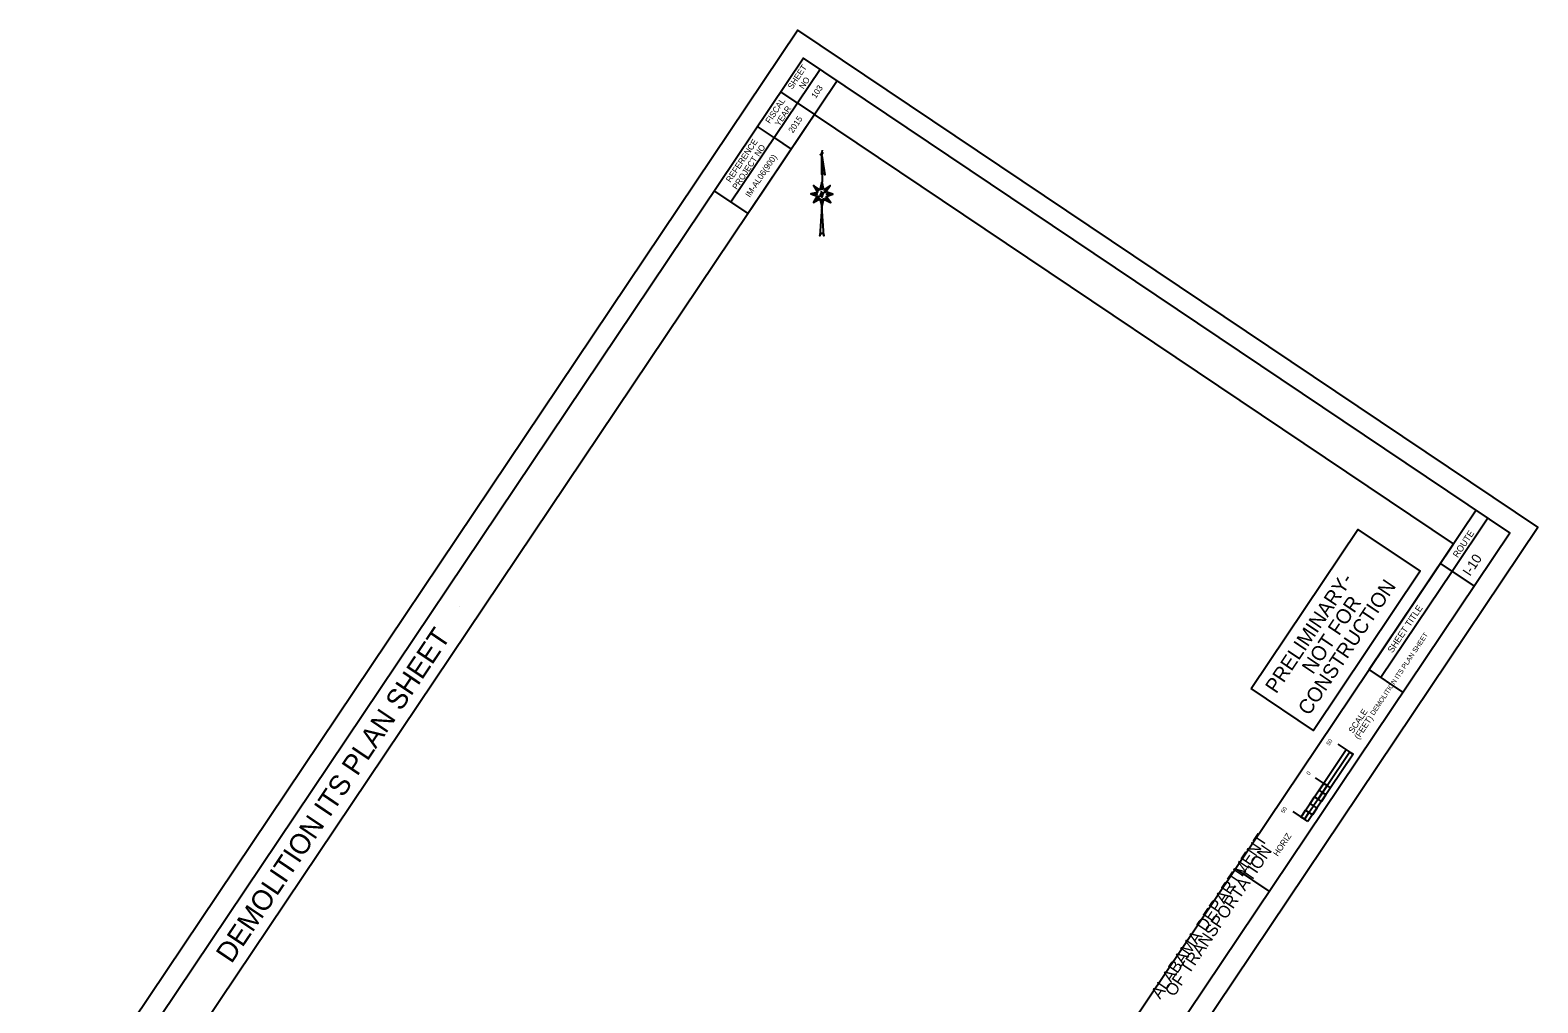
# Model space of a CAD drawing. Extents: x 1797253 to 1799113, y 249374 to 251399.
# Drawn here: x 1797253 to 1799113, y 250199 to 251399 of the extents above; entities that cross this region are included whole.
import ezdxf

# ---------------------------------------------------------------- set-up
doc = ezdxf.new("R2010")
doc.units = 0
for name, color, linetype in [('1', 7, 'Continuous'), ('ANNO-SHT', 7, 'Continuous'), ('ANNO-SYMB', 7, 'Continuous'), ('ANNO-TXT', 7, 'Continuous'), ('DRAINAGE', 7, 'Continuous'), ('Level 1', 7, 'Continuous'), ('Level 57', 7, 'Continuous'), ('Level 6', 7, 'Continuous'), ('Level 62', 7, 'Continuous'), ('SHT-BDR', 7, 'Continuous'), ('SHT-BNDRY', 7, 'Continuous')]:
    doc.layers.add(name, color=color, linetype=linetype)

# ---------------------------------------------------------------- blocks, each defined once
blk = doc.blocks.new('SC47208')
at = {"layer": 'Level 1'}
blk.add_line((0, 0), (0, 0), dxfattribs=at)

msp = doc.modelspace()

# ---------------------------------------------------------------- linework, layer by layer
at = {"layer": '1'}
msp.add_lwpolyline([(1798759.5, 250586.8), (1798891.3, 250783), (1798968.2, 250731.4), (1798836.4, 250535.1)], close=True, dxfattribs=at)
at = {"layer": 'ANNO-SYMB'}
for p, q in [((1798877, 250511.2), (1798821.2, 250428.2)), ((1798885.3, 250505.6), (1798867, 250517.9)), ((1798885.3, 250505.6), (1798829.5, 250422.6)), ((1798885.3, 250505.6), (1798881.1, 250508.4)), ((1798885.3, 250505.6), (1798881.1, 250508.4)), ((1798885.3, 250505.6), (1798881.1, 250508.4)), ((1798857.4, 250464.1), (1798839.1, 250476.4)), ((1798857.4, 250464.1), (1798839.1, 250476.4)), ((1798857.4, 250464.1), (1798839.1, 250476.4)), ((1798853.2, 250466.9), (1798842.1, 250450.3)), ((1798853.2, 250466.9), (1798849.1, 250469.7)), ((1798853.2, 250466.9), (1798849.1, 250469.7)), ((1798853.2, 250466.9), (1798849.1, 250469.7)), ((1798829.5, 250422.6), (1798811.3, 250434.9)), ((1798830.9, 250433.7), (1798826.8, 250436.5)), ((1798830.9, 250433.7), (1798826.8, 250436.5))]:
    msp.add_line(p, q, dxfattribs=at)
for points in [[(1798853.2, 250466.9), (1798881.1, 250508.4), (1798885.3, 250505.6), (1798857.4, 250464.1)], [(1798842.1, 250450.3), (1798847.7, 250458.6), (1798851.8, 250455.8), (1798846.2, 250447.5)], [(1798843.5, 250461.4), (1798849.1, 250469.7), (1798853.2, 250466.9), (1798847.7, 250458.6)], [(1798830.9, 250433.7), (1798836.5, 250442), (1798840.7, 250439.2), (1798835.1, 250430.9)], [(1798832.4, 250444.8), (1798837.9, 250453.1), (1798842.1, 250450.3), (1798836.5, 250442)], [(1798821.2, 250428.2), (1798826.8, 250436.5), (1798830.9, 250433.7), (1798825.4, 250425.4)]]:
    msp.add_lwpolyline(points, close=True, dxfattribs=at)
at = {"layer": 'ANNO-TXT'}
for p, q in [((1799007.5, 250731.4), (1799051.6, 250797.1)), ((1798919.6, 250600.6), (1799007.5, 250731.4))]:
    msp.add_line(p, q, dxfattribs=at)
at = {"layer": 'Level 57'}
msp.add_line((1798229.9, 251250.8), (1798229.7, 251248.3), dxfattribs=at)
for points in [[(1798230.9, 251247.3), (1798230.9, 251247.2), (1798230.9, 251247.1), (1798231, 251247.2), (1798231, 251247.4), (1798230.8, 251247.4), (1798230.5, 251247.2), (1798230.4, 251247.1), (1798230.2, 251246.8), (1798230.1, 251246.3), (1798229.8, 251245.8), (1798229.8, 251245.6), (1798229.7, 251245.2), (1798229.7, 251245.8), (1798229.6, 251246.7), (1798229.4, 251247.4), (1798229.4, 251246.8), (1798229.7, 251245.2), (1798229.6, 251246.8), (1798229.4, 251247.4), (1798229.3, 251246.8), (1798228.9, 251245.8), (1798228.6, 251245.2), (1798228.4, 251245.1), (1798228.1, 251245.1), (1798228, 251245.2), (1798228, 251245.4), (1798228.1, 251245.5), (1798228.2, 251245.4), (1798228.1, 251245.3)], [(1798229.7, 251244.3), (1798233.4, 251220.2), (1798233.3, 251220.9), (1798233.1, 251221.2), (1798232.7, 251221.6), (1798232.1, 251221.8), (1798231.8, 251221.9), (1798231.5, 251221.9), (1798231.1, 251221.9), (1798230.8, 251221.8), (1798230.5, 251221.6), (1798230.1, 251221.4), (1798229.9, 251221.1), (1798229.8, 251220.8), (1798229.8, 251220.7), (1798229.8, 251244.1), (1798229.9, 251211.2)], [(1798229.8, 251211.2), (1798229.7, 251202.3), (1798229.8, 251211.3), (1798227.1, 251201.7), (1798219.2, 251207.2), (1798225.3, 251200.5), (1798219.2, 251207.2), (1798224.2, 251198.7), (1798216.2, 251196.8), (1798223.8, 251196.6), (1798216.3, 251196.9), (1798224, 251194.1), (1798219.5, 251186.3), (1798225.2, 251192), (1798219.5, 251186.3), (1798227.3, 251190.6), (1798229.7, 251181.7), (1798229.6, 251190.1), (1798229.7, 251181.5), (1798231.7, 251190.5), (1798240.6, 251186.4), (1798231.6, 251190.5), (1798229.7, 251181.2), (1798227.3, 251145.3), (1798227.5, 251146.4), (1798227.8, 251147.2), (1798228.3, 251147.7), (1798228.9, 251148.2), (1798229.5, 251148.3), (1798230.1, 251148.3), (1798230.6, 251148.1), (1798231.1, 251147.8), (1798231.5, 251147.2), (1798231.9, 251146.6), (1798232, 251146.1), (1798232.2, 251145.2), (1798229.8, 251181.8), (1798231.5, 251190.6), (1798240.5, 251186.4), (1798233.6, 251191.6), (1798240.3, 251186.5), (1798235.2, 251193.6), (1798243.2, 251196.7), (1798235.5, 251196.6), (1798243.4, 251196.7), (1798234.6, 251199.4), (1798240.1, 251207.2), (1798233.6, 251200.9), (1798240.1, 251207.2), (1798232.1, 251201.7), (1798229.9, 251211.1)], [(1798233.7, 251199.2), (1798233.4, 251199), (1798233.8, 251198.8), (1798233.9, 251199.1), (1798233.8, 251199.5), (1798233.7, 251199.6), (1798233, 251199.5), (1798232.5, 251199.2), (1798231.4, 251198), (1798231.3, 251197.6), (1798230.9, 251196.4), (1798230.5, 251195.1), (1798230, 251194.2), (1798229.8, 251192.8), (1798229.8, 251194.6), (1798229.7, 251196.8), (1798229.6, 251198), (1798229.1, 251199.5), (1798229, 251197.8), (1798229.3, 251195.5), (1798229.5, 251194.1), (1798229.8, 251192.9), (1798229.8, 251194.9), (1798229.6, 251198.1), (1798229, 251199.5), (1798228.7, 251198), (1798228.1, 251196.4), (1798227.8, 251195.8), (1798227.6, 251194.9), (1798227.2, 251194.2), (1798226.9, 251193.6), (1798226.6, 251193.1), (1798225.8, 251192.7), (1798225.2, 251192.8), (1798224.9, 251193.1), (1798224.8, 251193.8), (1798225.2, 251194.1), (1798225.6, 251193.7), (1798225.3, 251193.5)]]:
    msp.add_lwpolyline(points, dxfattribs=at)
at = {"layer": 'Level 6'}
for p, q in [((1798227.5, 251350.4), (1798117.5, 251186.6)), ((1798248.5, 251336.3), (1798141.9, 251177.5)), ((1798199.3, 251309.1), (1798179.1, 251322.6)), ((1798199.3, 251309.1), (1798220.6, 251294.8)), ((1798171.2, 251266), (1798150.4, 251279.9)), ((1798171.2, 251266), (1798191.9, 251252.1)), ((1798097, 251200.4), (1798138.5, 251172.5)), ((1799037.2, 250806.8), (1798905.2, 250610.2))]:
    msp.add_line(p, q, dxfattribs=at)
at = {"layer": 'Level 62'}
msp.add_lwpolyline([(1798165.8, 249374.3), (1799113.4, 250785.7), (1798200.2, 251398.8), (1797252.5, 249987.5)], close=True, dxfattribs=at)
at = {"layer": 'SHT-BDR'}
msp.add_lwpolyline([(1798173.2, 249519.9), (1799009.3, 250765.2), (1798220.6, 251294.8), (1797384.4, 250049.4)], close=True, dxfattribs=at)
at = {"layer": 'SHT-BNDRY'}
for p, q in [((1799034.7, 250713.2), (1798993.1, 250741.1)), ((1798946.8, 250582.3), (1798905.2, 250610.2)), ((1798781.8, 250336.6), (1798740.3, 250364.5))]:
    msp.add_line(p, q, dxfattribs=at)
msp.add_lwpolyline([(1798179.9, 249440.1), (1799078.7, 250778.9), (1798207, 251364.2), (1797308.1, 250025.4)], close=True, dxfattribs=at)

# ---------------------------------------------------------------- block references
at = {"layer": 'DRAINAGE', "xscale": 1.000002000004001, "yscale": 1.000002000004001, "rotation": -60.294516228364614}
msp.add_blockref('SC47208', (1797781.9, 250687.9), dxfattribs=at)
msp.add_blockref('SC47208', (1797781.9, 250687.9), dxfattribs=at)

# ---------------------------------------------------------------- texts
at = {"layer": '1'}
for s, p in [('PRELIMINARY-', (1798790.6, 250579.4)), ('CONSTRUCTION', (1798831, 250552.3)), ('NOT FOR', (1798835.9, 250603.2))]:
    msp.add_text(s, height=18, rotation=56.1222, dxfattribs=at).set_placement(p)
at = {"layer": 'ANNO-SHT'}
for s, height, p in [('103', 7.45, (1798222.2, 251314)), ('2015', 7.45, (1798193.9, 251271.2)), ('IM-AL06(900)', 7.449, (1798140.8, 251191.9)), ('  I-10  ', 12, (1799024.7, 250717)), ('             DEMOLITION ITS PLAN SHEET             ', 24.998, (1797433.7, 250146.1)), ('             DEMOLITION ITS PLAN SHEET             ', 6, (1798894.4, 250528.2))]:
    msp.add_text(s, height=height, rotation=56.1222, dxfattribs=at).set_placement(p)
at = {"layer": 'ANNO-SYMB'}
for s, height, p in [('SCALE', 7.5, (1798885.3, 250531)), ('(FEET)', 7.5, (1798892.4, 250523.3)), (' 50', 5, (1798855, 250514.4)), ('0', 5, (1798831.4, 250479.3)), ('0', 5, (1798831.4, 250479.3)), ('0', 5, (1798831.4, 250479.3)), (' 50', 5, (1798798.8, 250430.7)), ('HORIZ', 7.5, (1798792.4, 250379.1))]:
    msp.add_text(s, height=height, rotation=56.1794, dxfattribs=at).set_placement(p)
at = {"layer": 'ANNO-TXT'}
for s, height, rotation, p in [('ROUTE', 8, 56.1222, (1799014.5, 250747.4)), ('SHEET TITLE', 8, 56.1222, (1798934, 250630)), ('ALABAMA DEPARTMENT', 15, 56.1221, (1798647.2, 250202.6)), ('OF TRANSPORTATION', 15, 56.1221, (1798664.3, 250205.6))]:
    msp.add_text(s, height=height, rotation=rotation, dxfattribs=at).set_placement(p)
at = {"layer": 'Level 6'}
for s, p in [('SHEET', (1798193.2, 251325.4)), ('NO', (1798207.1, 251325.5)), ('FISCAL', (1798165.5, 251282.9)), ('YEAR', (1798177.3, 251279.8)), ('REFERENCE', (1798116.8, 251210.4)), ('PROJECT NO', (1798124.7, 251201.5))]:
    msp.add_text(s, height=7.44, rotation=56.1222, dxfattribs=at).set_placement(p)

doc.saveas('drawing.dxf')
